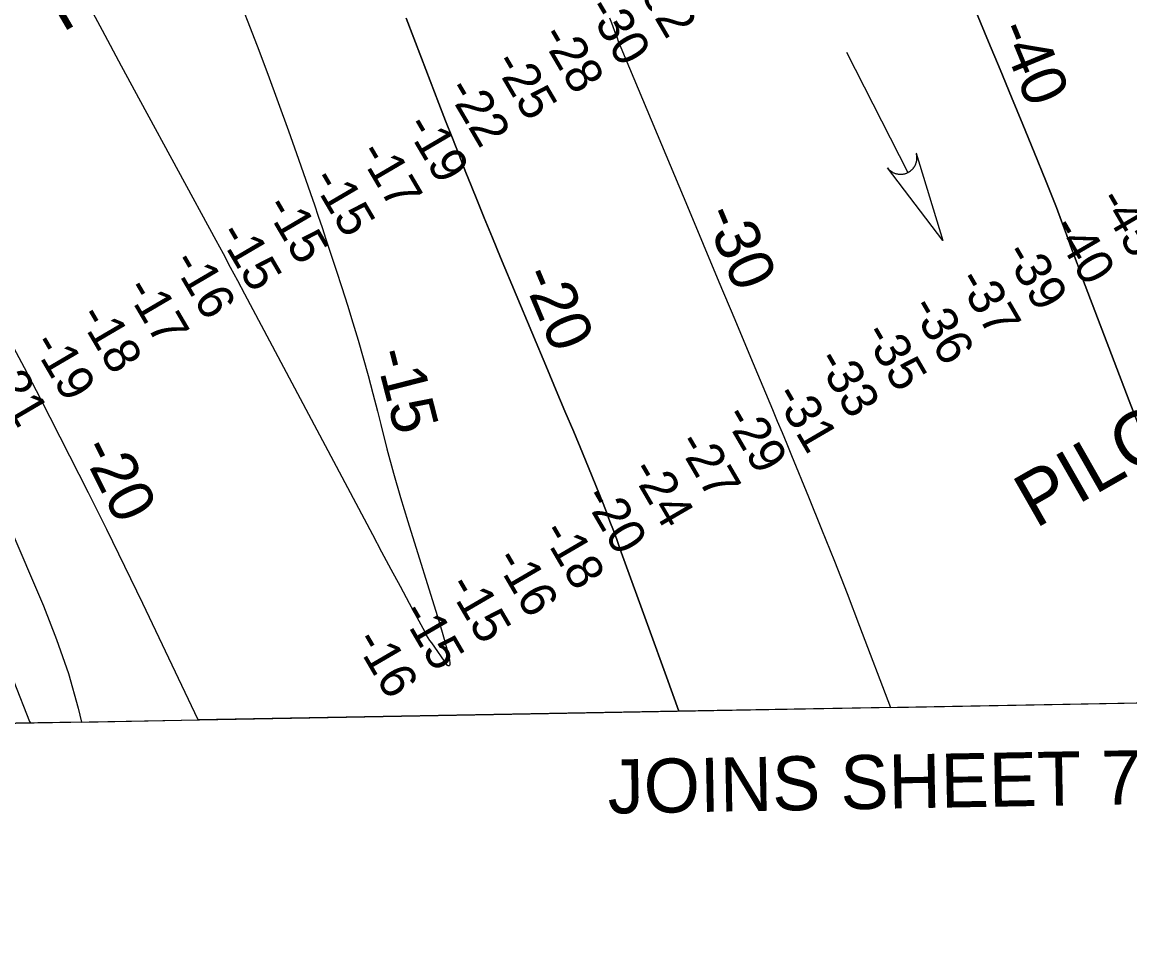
# Model space of a CAD drawing. Extents: x 3914892 to 3953151, y 242587 to 268572.
# Drawn here: x 3940742 to 3942793, y 248020 to 249705 of the extents above; entities that cross this region are included whole.
import ezdxf

# ---------------------------------------------------------------- set-up
doc = ezdxf.new("R2010")
doc.units = 0
for name, color, linetype in [('V-ANNO-TEXT', 7, 'Continuous'), ('V-CHAN-NAID', 7, 'Continuous'), ('V-GRID-FRAM', 7, 'Continuous'), ('V-RIVR-RANG', 7, 'Continuous'), ('V-STRM-FLOW', 7, 'Continuous'), ('V-TOPO-DPTH', 7, 'Continuous'), ('V-TOPO-MAJR-IDEN', 7, 'Continuous'), ('V-TOPO-MINR', 7, 'Continuous')]:
    doc.layers.add(name, color=color, linetype=linetype)

msp = doc.modelspace()

# ---------------------------------------------------------------- linework, layer by layer
at = {"layer": 'V-GRID-FRAM'}
msp.add_lwpolyline([(3918836.6, 266200.2), (3950733.3, 266770.9), (3951066.5, 248591.3), (3919153.9, 248020.4), (3918836.6, 266200.2)], dxfattribs=at)
at = {"layer": 'V-STRM-FLOW'}
msp.add_line((3942267.8, 249649.2), (3942381.8, 249426.3), dxfattribs=at)
msp.add_lwpolyline([(3942397.1, 249462.2), (3942446.3, 249300.2), (3942343.7, 249434.9), (3942345.7, 249432.6), (3942347.8, 249430.5), (3942348.7, 249429.8), (3942349.5, 249429.1), (3942350.6, 249428.4), (3942351.6, 249427.7), (3942352.5, 249427.2), (3942353.7, 249426.5), (3942355.1, 249425.8), (3942355.9, 249425.4), (3942357, 249425), (3942358.3, 249424.5), (3942359.4, 249424.2), (3942360.6, 249423.8), (3942361.4, 249423.7), (3942362.3, 249423.5), (3942363.4, 249423.3), (3942364.4, 249423.2), (3942365.4, 249423.1), (3942366.2, 249423), (3942367.4, 249423), (3942368.6, 249423), (3942369.5, 249423), (3942370.6, 249423.1), (3942371.6, 249423.2), (3942372.4, 249423.3), (3942373.1, 249423.4), (3942374, 249423.6), (3942375.1, 249423.8), (3942376, 249424), (3942377, 249424.3), (3942377.8, 249424.6), (3942378.8, 249425), (3942379.5, 249425.3), (3942380.6, 249425.7), (3942381.8, 249426.3), (3942382.2, 249426.5), (3942382.7, 249426.8), (3942383.4, 249427.2), (3942384, 249427.5), (3942384.6, 249427.9), (3942385.1, 249428.3), (3942385.8, 249428.7), (3942386.2, 249429.1), (3942386.9, 249429.5), (3942387.4, 249430), (3942387.8, 249430.4), (3942388.8, 249431.3), (3942389.4, 249431.8), (3942389.7, 249432.1), (3942390.3, 249432.7), (3942390.8, 249433.2), (3942391.3, 249433.8), (3942391.8, 249434.5), (3942392.3, 249435.2), (3942392.7, 249435.7), (3942393.1, 249436.2), (3942393.5, 249436.8), (3942393.8, 249437.4), (3942394.3, 249438.1), (3942394.7, 249438.8), (3942395, 249439.5), (3942395.5, 249440.4), (3942395.8, 249441.1), (3942396.1, 249441.8), (3942396.4, 249442.6), (3942396.6, 249443.2), (3942396.9, 249443.9), (3942397.2, 249444.9), (3942397.2, 249444.9), (3942397.4, 249445.5), (3942397.5, 249445.9), (3942397.6, 249446.6), (3942397.8, 249447.4), (3942398, 249448.1), (3942398.1, 249448.7), (3942398.2, 249449.5), (3942398.3, 249450.3), (3942398.3, 249450.8), (3942398.4, 249451.5), (3942398.4, 249452.5), (3942398.4, 249453), (3942398.4, 249453.5), (3942398.4, 249453.9), (3942398.4, 249454.4), (3942398.4, 249455.1), (3942398.3, 249455.7), (3942398.3, 249456.4), (3942398.2, 249457), (3942398.1, 249457.8), (3942398, 249458.3), (3942397.9, 249459.1), (3942397.7, 249460), (3942397.6, 249460.7), (3942397.4, 249461.2), (3942397.3, 249461.7), (3942397.2, 249462)], close=True, dxfattribs=at)
at = {"layer": 'V-TOPO-DPTH'}
msp.add_line((3940852.1, 248408.7), (3941067.8, 248412.6), dxfattribs=at)
for points in [[(3942824.6, 248917.7), (3942791.2, 249003.3), (3942758.4, 249089.1), (3942702.1, 249238.1), (3942697.8, 249249.5), (3942693.6, 249260.9), (3942689.4, 249272.4), (3942685.2, 249283.9), (3942675.3, 249311.2), (3942666, 249336.3), (3942656.6, 249361.3), (3942646.8, 249386.2), (3942636.8, 249411), (3942615.2, 249463.8), (3942594.3, 249514.9), (3942573.3, 249566), (3942552.2, 249617.1), (3942531.1, 249668.1), (3942478.9, 249794.3)], [(3942478.9, 249794.3), (3942531.1, 249668.1), (3942552.2, 249617.1), (3942573.3, 249566), (3942594.3, 249514.9), (3942615.2, 249463.8), (3942636.8, 249411), (3942646.8, 249386.2), (3942656.6, 249361.3), (3942666, 249336.3), (3942675.3, 249311.2), (3942685.2, 249283.9), (3942689.4, 249272.4), (3942693.6, 249260.9), (3942697.8, 249249.5), (3942702.1, 249238.1), (3942758.4, 249089.1), (3942791.2, 249003.3), (3942824.6, 248917.7)], [(3941452.9, 249711.8), (3941481.4, 249637.9), (3941513.6, 249554), (3941526, 249522), (3941538.4, 249490.1), (3941550.9, 249458.2), (3941563.5, 249426.3), (3941567.6, 249416), (3941582.4, 249379.1), (3941597.4, 249342.2), (3941612.5, 249305.4), (3941627.8, 249268.6), (3941714.7, 249061.4), (3941730.8, 249022.9), (3941746.9, 248984.4), (3941763, 248945.9), (3941779, 248907.4), (3941797.4, 248863.3), (3941804.2, 248846.9), (3941810.9, 248830.3), (3941817.4, 248813.7), (3941823.9, 248797.1), (3941830.2, 248780.4), (3941836.5, 248763.7), (3941842.6, 248747), (3941848.7, 248730.2), (3941901.8, 248582.8), (3941934.5, 248492.3), (3941957.6, 248428.8)], [(3942349.6, 248435.9), (3941957.6, 248428.8), (3941934.5, 248492.3), (3941901.8, 248582.8), (3941848.7, 248730.2), (3941842.6, 248747), (3941836.5, 248763.7), (3941830.2, 248780.4), (3941823.9, 248797.1), (3941817.4, 248813.7), (3941810.9, 248830.3), (3941804.2, 248846.9), (3941797.4, 248863.3), (3941779, 248907.4), (3941763, 248945.9), (3941746.9, 248984.4), (3941730.8, 249022.9), (3941714.7, 249061.4), (3941627.8, 249268.6), (3941612.5, 249305.4), (3941597.4, 249342.2), (3941582.4, 249379.1), (3941567.6, 249416), (3941563.5, 249426.3), (3941550.9, 249458.2), (3941538.4, 249490.1), (3941526, 249522), (3941513.6, 249554), (3941481.4, 249637.9), (3941452.9, 249711.8)], [(3941829.5, 249712.6), (3941832.8, 249703.4), (3941841, 249681.3), (3941843.2, 249675.3), (3941845.5, 249669.4), (3941847.9, 249663.4), (3941850.3, 249657.5), (3941973.5, 249363), (3942002.7, 249293.3), (3942031.9, 249223.6), (3942061.1, 249153.9), (3942090.3, 249084.2), (3942131, 248987.2), (3942139.9, 248966), (3942148.7, 248944.9), (3942157.5, 248923.7), (3942166.2, 248902.5), (3942197.6, 248825.8), (3942221.8, 248766.2), (3942245.7, 248706.5), (3942269.1, 248646.5), (3942292.2, 248586.5), (3942349.6, 248435.9)], [(3941829.5, 249712.6), (3941832.8, 249703.4), (3941841, 249681.3), (3941843.2, 249675.3), (3941845.5, 249669.4), (3941847.9, 249663.4), (3941850.3, 249657.5), (3941973.5, 249363), (3942002.7, 249293.3), (3942031.9, 249223.6), (3942061.1, 249153.9), (3942090.3, 249084.2), (3942131, 248987.2), (3942139.9, 248966), (3942148.7, 248944.9), (3942157.5, 248923.7), (3942166.2, 248902.5), (3942197.6, 248825.8), (3942221.8, 248766.2), (3942245.7, 248706.5), (3942269.1, 248646.5), (3942292.2, 248586.5), (3942349.6, 248435.9)], [(3941957.6, 248428.8), (3941067.8, 248412.6), (3940965.1, 248628.4), (3940932.1, 248696.9), (3940898.8, 248765.2), (3940864.8, 248833.3), (3940830.5, 248901.1), (3940775.8, 249008.1), (3940768.5, 249022.3), (3940761.2, 249036.5), (3940753.7, 249050.6), (3940746.2, 249064.7), (3940432.7, 249650.7)], [(3941067.8, 248412.6), (3940965.1, 248628.4), (3940932.1, 248696.9), (3940898.8, 248765.2), (3940864.8, 248833.3), (3940830.5, 248901.1), (3940775.8, 249008.1), (3940768.5, 249022.3), (3940761.2, 249036.5), (3940753.7, 249050.6), (3940746.2, 249064.7), (3940432.7, 249650.7)], [(3940650.9, 248928.3), (3940781.3, 248623.8), (3940805.7, 248561.6), (3940827.7, 248498.7), (3940845.8, 248434.5), (3940852.1, 248408.7)], [(3940650.9, 248928.3), (3940781.3, 248623.8), (3940805.7, 248561.6), (3940827.7, 248498.7), (3940845.8, 248434.5), (3940852.1, 248408.7)], [(3942349.6, 248435.9), (3943014.5, 248448)], [(3940852.1, 248408.7), (3940689.3, 248405.8)]]:
    msp.add_lwpolyline(points, dxfattribs=at)
at = {"layer": 'V-TOPO-MINR'}
for points in [[(3942478.9, 249794.3), (3942531.1, 249668.1), (3942552.2, 249617.1), (3942573.3, 249566), (3942594.3, 249514.9), (3942615.2, 249463.8), (3942636.8, 249411), (3942646.8, 249386.2), (3942656.6, 249361.3), (3942666, 249336.3), (3942675.3, 249311.2), (3942685.2, 249283.9), (3942689.4, 249272.4), (3942693.6, 249260.9), (3942697.8, 249249.5), (3942702.1, 249238.1), (3942758.4, 249089.1), (3942791.2, 249003.3), (3942824.6, 248917.7)], [(3941135.8, 249767.8), (3941177, 249660.7), (3941196.8, 249608.5), (3941216.2, 249556.1), (3941235.1, 249503.5), (3941253.7, 249450.9), (3941275.7, 249387.2), (3941282.9, 249366.2), (3941290.1, 249345.2), (3941297.1, 249324.2), (3941304.1, 249303.1), (3941323.2, 249245.5), (3941333.7, 249213.1), (3941344, 249180.7), (3941354, 249148.2), (3941363.8, 249115.6), (3941373.3, 249082.9), (3941382.5, 249050.1), (3941391.2, 249017.3), (3941399.6, 248984.3), (3941405.7, 248959.8), (3941417.4, 248914.6), (3941429.6, 248869.6), (3941442.5, 248824.8), (3941456, 248780.2), (3941513.5, 248596), (3941516.1, 248587.7), (3941518.5, 248579.3), (3941520.9, 248570.9), (3941523.3, 248562.5), (3941531.8, 248530.9), (3941532.7, 248527), (3941533.4, 248523), (3941533.8, 248519.1), (3941534, 248515.1), (3941533.2, 248513.5), (3941532.2, 248512.6), (3941530.9, 248512.8), (3941529.3, 248513.6), (3941500.2, 248555.2), (3941497, 248560), (3941493.8, 248564.9), (3941490.8, 248569.9), (3941487.9, 248575), (3941459.2, 248628.1), (3941442.1, 248659.8), (3941425, 248691.5), (3941408.1, 248723.3), (3941391.1, 248755.1), (3941154.5, 249200.7), (3941141.2, 249225.6), (3941127.9, 249250.5), (3941114.5, 249275.4), (3941101, 249300.3), (3940961.7, 249556.9), (3940926.1, 249622.8), (3940890.8, 249688.9), (3940855.7, 249755.1)], [(3941452.9, 249711.8), (3941481.4, 249637.9), (3941513.6, 249554), (3941526, 249522), (3941538.4, 249490.1), (3941550.9, 249458.2), (3941563.5, 249426.3), (3941567.6, 249416), (3941582.4, 249379.1), (3941597.4, 249342.2), (3941612.5, 249305.4), (3941627.8, 249268.6), (3941714.7, 249061.4), (3941730.8, 249022.9), (3941746.9, 248984.4), (3941763, 248945.9), (3941779, 248907.4), (3941797.4, 248863.3), (3941804.2, 248846.9), (3941810.9, 248830.3), (3941817.4, 248813.7), (3941823.9, 248797.1), (3941830.2, 248780.4), (3941836.5, 248763.7), (3941842.6, 248747), (3941848.7, 248730.2), (3941901.8, 248582.8), (3941934.5, 248492.3), (3941957.6, 248428.8)], [(3941829.5, 249712.6), (3941832.8, 249703.4), (3941841, 249681.3), (3941843.2, 249675.3), (3941845.5, 249669.4), (3941847.9, 249663.4), (3941850.3, 249657.5), (3941973.5, 249363), (3942002.7, 249293.3), (3942031.9, 249223.6), (3942061.1, 249153.9), (3942090.3, 249084.2), (3942131, 248987.2), (3942139.9, 248966), (3942148.7, 248944.9), (3942157.5, 248923.7), (3942166.2, 248902.5), (3942197.6, 248825.8), (3942221.8, 248766.2), (3942245.7, 248706.5), (3942269.1, 248646.5), (3942292.2, 248586.5), (3942349.6, 248435.9)], [(3941067.8, 248412.6), (3940965.1, 248628.4), (3940932.1, 248696.9), (3940898.8, 248765.2), (3940864.8, 248833.3), (3940830.5, 248901.1), (3940775.8, 249008.1), (3940768.5, 249022.3), (3940761.2, 249036.5), (3940753.7, 249050.6), (3940746.2, 249064.7), (3940432.7, 249650.7)], [(3940650.9, 248928.3), (3940781.3, 248623.8), (3940805.7, 248561.6), (3940827.7, 248498.7), (3940845.8, 248434.5), (3940852.1, 248408.7)], [(3940726.3, 248483.8), (3940755.9, 248410), (3940757.2, 248407)]]:
    msp.add_lwpolyline(points, dxfattribs=at)

# ---------------------------------------------------------------- texts
at = {"layer": 'V-ANNO-TEXT'}
msp.add_text('JOINS SHEET 72', height=100, rotation=1.025, dxfattribs=at).set_placement((3941826.6, 248239.2))
at = {"layer": 'V-CHAN-NAID'}
for s, rotation, p in [('PILOTTOWN - CHARLIE', 30.2462, (3940816, 249684.7)), ('PILOTTOWN RANGE A', 29.7053, (3942618, 248766.4))]:
    msp.add_text(s, height=100, rotation=rotation, dxfattribs=at).set_placement(p)
at = {"layer": 'V-RIVR-RANG'}
for s, rotation, p in [('-32', 300.4126, (3941871.1, 249782.2)), ('-30', 300.4126, (3941785.6, 249730.2)), ('-28', 300.4126, (3941699.7, 249679.1)), ('-25', 300.4126, (3941612.8, 249629.6)), ('-22', 300.4126, (3941525.9, 249580.1)), ('-19', 300.4126, (3941449.5, 249512.7)), ('-17', 300.4126, (3941362.9, 249462.7)), ('-15', 300.4126, (3941275.9, 249413.4)), ('-45', 300.2615, (3942731.9, 249375.5)), ('-15', 300.4126, (3941189.5, 249363)), ('-15', 300.4126, (3941103.1, 249312.6)), ('-40', 300.2615, (3942645.8, 249324.6)), ('-39', 300.2615, (3942558, 249276.7)), ('-16', 300.4126, (3941017.6, 249260.9)), ('-17', 300.4126, (3940931.1, 249210.7)), ('-37', 300.2615, (3942471.2, 249227)), ('-36', 300.2615, (3942384.8, 249176.6)), ('-18', 300.4126, (3940844.6, 249160.5)), ('-19', 300.4126, (3940758.6, 249109.4)), ('-35', 300.2615, (3942297.5, 249127.8)), ('-33', 300.2615, (3942210.2, 249079)), ('-21', 300.4126, (3940670.6, 249061.7)), ('-31', 300.2615, (3942132.4, 249014)), ('-29', 300.2615, (3942039.2, 248975.2)), ('-27', 300.2615, (3941952.5, 248925.5)), ('-24', 300.2615, (3941866.2, 248874.8)), ('-20', 300.2615, (3941779.2, 248825.5)), ('-18', 300.2615, (3941701.4, 248760.6)), ('-16', 300.2615, (3941615.1, 248709.9)), ('-15', 300.2615, (3941527.8, 248661.1)), ('-15', 300.2615, (3941441.3, 248610.9)), ('-16', 300.2615, (3941355.6, 248559.4))]:
    msp.add_text(s, height=67, rotation=rotation, dxfattribs=at).set_placement(p)
at = {"layer": 'V-TOPO-MAJR-IDEN'}
for s, rotation, p in [('-40', 292.4104, (3942545.2, 249691.2)), ('-30', 292.7212, (3942002.8, 249349.3)), ('-20', 292.7435, (3941664.9, 249236.4)), ('-15', 284.3542, (3941394.4, 249092.4)), ('-20', 296.5068, (3940848.4, 248915))]:
    msp.add_text(s, height=83, rotation=rotation, dxfattribs=at).set_placement(p)

doc.saveas('drawing.dxf')
